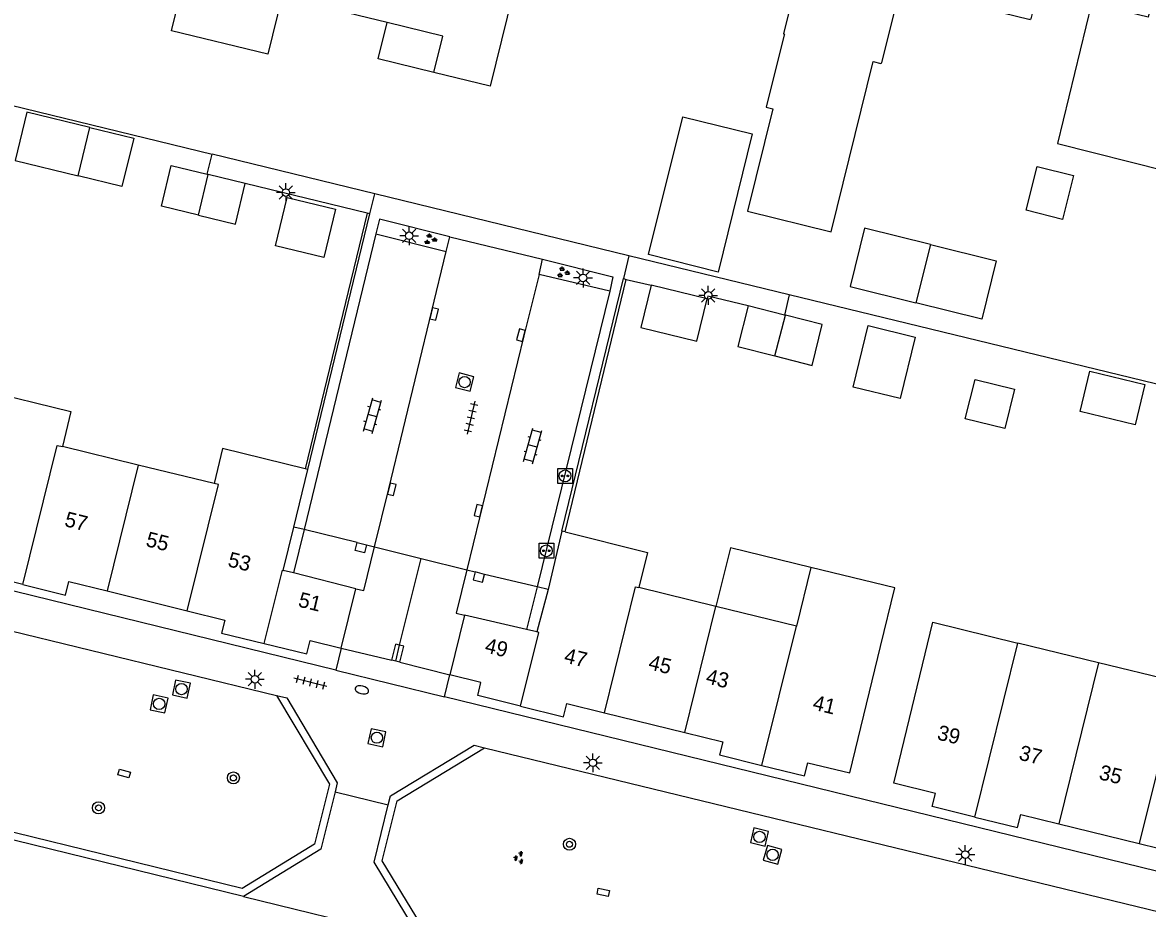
# Model space of a CAD drawing. Extents: x 125000 to 129004, y 397500 to 399008.
# Drawn here: x 126600.2 to 126674.8, y 398127.6 to 398186.4 of the extents above; entities that cross this region are included whole.
import ezdxf

# ---------------------------------------------------------------- set-up
doc = ezdxf.new("R2010")
doc.units = 0
for name, color, linetype in [('gg-afsc-erfafscheiding', 7, 'Continuous'), ('gg-afsc-hekwerk', 7, 'Continuous'), ('gg-anno-huisnummerreeks BGT', 7, 'Continuous'), ('gg-bbg-bijgebouw', 7, 'Continuous'), ('gg-bbg-gedigitaliseerde bebouwing', 7, 'Continuous'), ('gg-bbg-gedigitaliseerde bijgebouw', 7, 'Continuous'), ('gg-bbg-hoofdgebouw', 7, 'Continuous'), ('gg-bbg-luifel en loopbrug', 7, 'Continuous'), ('gg-bbg-onder overbouw', 7, 'Continuous'), ('gg-bbg-pand overbouw', 7, 'Continuous'), ('gg-bbg-pilaar onder overbouw', 7, 'Continuous'), ('gg-bbg-pilaar pand', 7, 'Continuous'), ('gg-bbg-tussenscheiding', 7, 'Continuous'), ('gg-bbg-tussenscheiding niveau 01', 7, 'Continuous'), ('gg-knt-verharding', 7, 'Continuous'), ('gg-knt-verharding onder overbouw', 7, 'Continuous'), ('gt-grn-weggrens', 7, 'Continuous'), ('gt-symb-boom', 7, 'Continuous'), ('gt-symb-brandkraan', 7, 'Continuous'), ('gt-symb-groenvak', 7, 'Continuous'), ('gt-symb-klinker verharding', 7, 'Continuous'), ('gt-symb-kolk', 7, 'Continuous'), ('gt-symb-kolk center center', 7, 'Continuous'), ('gt-symb-laadpunt elektrisch vervoer', 7, 'Continuous'), ('gt-symb-lichtmast', 7, 'Continuous'), ('gt-symb-rioolschacht', 7, 'Continuous'), ('gt-symb-tegel verharding', 7, 'Continuous')]:
    doc.layers.add(name, color=color, linetype=linetype)

# ---------------------------------------------------------------- blocks, each defined once
blk = doc.blocks.new('gt0-LMAST')
at = {"layer": 'gt-symb-lichtmast'}
for p, q in [((-0.182, 0.173), (-0.447, 0.438)), ((-0.005, 0.246), (-0.005, 0.621)), ((0.172, 0.173), (0.437, 0.438)), ((-0.255, -0.004), (-0.63, -0.004)), ((-0.182, -0.181), (-0.447, -0.446)), ((-0.005, -0.254), (-0.005, -0.629)), ((0.437, -0.446), (0.172, -0.181)), ((0.245, -0.004), (0.62, -0.004))]:
    blk.add_line(p, q, dxfattribs=at)
blk.add_circle((-0.005, -0.004), 0.25, dxfattribs=at)
blk = doc.blocks.new('gt0-GRVAK')
at = {"layer": 'gt-symb-groenvak'}
for p, q in [((-0.11, 0.189), (-0.228, 0.24)), ((-0.182, 0.153), (0.088, 0.153)), ((-0.091, 0.211), (-0.156, 0.322)), ((-0.047, 0.214), (-0.047, 0.393)), ((-0.004, 0.211), (0.061, 0.322)), ((0.015, 0.189), (0.133, 0.24)), ((0.262, -0.052), (0.197, 0.059)), ((0.305, -0.049), (0.305, 0.13)), ((0.349, -0.052), (0.414, 0.059)), ((-0.245, -0.228), (-0.363, -0.177)), ((-0.318, -0.264), (-0.047, -0.264)), ((-0.226, -0.206), (-0.291, -0.095)), ((-0.183, -0.203), (-0.183, -0.024)), ((-0.139, -0.206), (-0.074, -0.095)), ((-0.12, -0.228), (-0.002, -0.177)), ((0.243, -0.074), (0.125, -0.023)), ((0.17, -0.11), (0.441, -0.11)), ((0.368, -0.074), (0.486, -0.023))]:
    blk.add_line(p, q, dxfattribs=at)
blk = doc.blocks.new('gt0-KOLK')
at = {"layer": 'gt-symb-kolk'}
blk.add_lwpolyline([(0, 0), (0.375, 0), (0.375, 0.4), (-0.375, 0.4), (-0.375, 0), (0, 0)], dxfattribs=at)
blk = doc.blocks.new('gt0-LEV')
at = {"layer": 'gt-symb-laadpunt elektrisch vervoer'}
blk.add_lwpolyline([(-0.486, 0.501), (0.486, 0.501), (0.486, -0.499), (-0.486, -0.499)], close=True, dxfattribs=at)
for centre, radius in [((0, 0), 0.393), ((-0.186, 0), 0.0566), ((0.186, 0), 0.0566)]:
    blk.add_circle(centre, radius, dxfattribs=at)
blk = doc.blocks.new('gt0-KL1')
at = {"layer": 'gt-symb-klinker verharding'}
for p, q in [((-1.15, 0.3), (1.15, 0.3)), ((-1, -0.3), (-1, 0.3)), ((-0.5, 0.3), (-0.5, 0.45)), ((0, -0.3), (0, 0.3)), ((0.5, 0.3), (0.5, 0.45)), ((1, -0.3), (1, 0.3)), ((-1.15, -0.3), (1.15, -0.3)), ((-0.5, -0.45), (-0.5, -0.3)), ((0.5, -0.45), (0.5, -0.3))]:
    blk.add_line(p, q, dxfattribs=at)
blk = doc.blocks.new('gt0-TEG1')
at = {"layer": 'gt-symb-tegel verharding'}
for p, q in [((-1.125, 0), (1.125, 0)), ((-0.9, -0.25), (-0.9, 0.25)), ((-0.45, -0.25), (-0.45, 0.25)), ((0, -0.25), (0, 0.25)), ((0.45, -0.25), (0.45, 0.25)), ((0.9, -0.25), (0.9, 0.25))]:
    blk.add_line(p, q, dxfattribs=at)
blk = doc.blocks.new('gt0-RS')
at = {"layer": 'gt-symb-rioolschacht'}
blk.add_lwpolyline([(-0.5, -0.5), (0.5, -0.5), (0.5, 0.5), (-0.5, 0.5)], close=True, dxfattribs=at)
blk.add_circle((0, 0), 0.375, dxfattribs=at)
blk = doc.blocks.new('gt0-KOLKCC')
at = {"layer": 'gt-symb-kolk center center'}
blk.add_lwpolyline([(-0.375, 0.2), (0.375, 0.2), (0.375, -0.2), (-0.375, -0.2)], close=True, dxfattribs=at)
blk = doc.blocks.new('gt0-BR')
at = {"layer": 'gt-symb-brandkraan'}
for centre, radius, start, end in [((-0.244, 0), 0.206, 107.56694, 252.43307), ((0.599, -2.664), 3, 106.89205, 107.56694), ((0, -0.691), 0.938, 73.10799, 106.89205), ((-0.599, -2.664), 3, 72.43309, 73.10799), ((0.244, 0), 0.206, 287.56695, 72.43309), ((0.599, 2.664), 3, 252.43307, 253.10797), ((0, 0.691), 0.938, 253.10797, 286.89206), ((-0.599, 2.664), 3, 286.89206, 287.56695)]:
    blk.add_arc(centre, radius, start, end, dxfattribs=at)
blk = doc.blocks.new('gt0-BOOM')
at = {"layer": 'gt-symb-boom'}
for radius in [0.4, 0.2]:
    blk.add_circle((0, 0), radius, dxfattribs=at)

msp = doc.modelspace()

# ---------------------------------------------------------------- linework, layer by layer
at = {"layer": 'gg-afsc-erfafscheiding'}
for p, q in [((126612.44, 398176.327), (126612.768, 398177.653)), ((126623.054, 398173.738), (126614.949, 398175.717)), ((126640.226, 398169.348), (126641.881, 398168.958)), ((126651.043, 398168.332), (126650.74, 398166.986))]:
    msp.add_line(p, q, dxfattribs=at)
msp.add_lwpolyline([(126648.323, 398167.602), (126645.649, 398168.229), (126645.606, 398168.053)], dxfattribs=at)
at = {"layer": 'gg-afsc-hekwerk'}
for p, q in [((126588.032, 398183.677), (126612.768, 398177.653)), ((126623.55, 398175.027), (126612.768, 398177.653)), ((126640.415, 398170.92), (126623.55, 398175.027)), ((126623.054, 398173.738), (126618.927, 398156.788)), ((126651.043, 398168.332), (126640.415, 398170.92)), ((126636.179, 398152.601), (126640.226, 398169.348)), ((126676.075, 398162.236), (126651.043, 398168.332))]:
    msp.add_line(p, q, dxfattribs=at)
at = {"layer": 'gg-bbg-bijgebouw'}
for p, q in [((126612.509, 398176.31), (126612.44, 398176.327)), ((126614.949, 398175.717), (126612.509, 398176.31)), ((126645.606, 398168.053), (126641.881, 398168.958)), ((126650.74, 398166.986), (126648.323, 398167.602)), ((126650.79, 398166.973), (126650.74, 398166.986))]:
    msp.add_line(p, q, dxfattribs=at)
for points in [[(126643.991, 398180.132), (126648.588, 398179.003), (126646.331, 398169.819), (126641.712, 398171.01), (126643.991, 398180.132)], [(126611.852, 398173.601), (126609.396, 398174.196), (126610.053, 398176.907), (126612.44, 398176.327)], [(126611.852, 398173.601), (126614.307, 398173.005), (126614.949, 398175.717)], [(126641.881, 398168.958), (126641.204, 398166.152), (126644.925, 398165.248), (126645.606, 398168.053)], [(126648.323, 398167.602), (126647.635, 398164.898), (126650.101, 398164.269)], [(126650.101, 398164.269), (126652.566, 398163.64), (126653.235, 398166.351), (126650.79, 398166.973)]]:
    msp.add_lwpolyline(points, dxfattribs=at)
at = {"layer": 'gg-bbg-gedigitaliseerde bebouwing'}
for p, q in [((126652.473, 398150.24), (126651.526, 398146.354)), ((126655.056, 398136.613), (126657.109, 398144.993))]:
    msp.add_line(p, q, dxfattribs=at)
for points in [[(126650.71, 398185.575), (126649.525, 398180.77), (126649.962, 398180.662), (126648.286, 398173.865), (126653.82, 398172.5), (126656.607, 398183.801)], [(126657.109, 398144.993), (126658.056, 398148.879), (126652.473, 398150.24)]]:
    msp.add_lwpolyline(points, dxfattribs=at)
at = {"layer": 'gg-bbg-gedigitaliseerde bijgebouw'}
for p, q in [((126603.869, 398176.211), (126604.65, 398179.418)), ((126660.415, 398171.672), (126659.45, 398167.79))]:
    msp.add_line(p, q, dxfattribs=at)
for points in [[(126604.65, 398179.418), (126607.564, 398178.708), (126606.784, 398175.502), (126603.869, 398176.211)], [(126669.912, 398176.232), (126669.176, 398173.323), (126666.753, 398173.936), (126667.488, 398176.844), (126669.912, 398176.232)], [(126620.944, 398174.005), (126620.164, 398170.798), (126616.957, 398171.579), (126617.738, 398174.785), (126620.944, 398174.005)], [(126660.415, 398171.672), (126664.782, 398170.587), (126663.817, 398166.705), (126659.45, 398167.79)], [(126656.286, 398166.279), (126659.395, 398165.522), (126658.401, 398161.441), (126655.292, 398162.198), (126656.286, 398166.279)], [(126670.996, 398163.26), (126674.639, 398162.372), (126673.989, 398159.701), (126670.345, 398160.588), (126670.996, 398163.26)], [(126663.369, 398162.714), (126665.992, 398162.071), (126665.349, 398159.448), (126662.726, 398160.091), (126663.369, 398162.714)]]:
    msp.add_lwpolyline(points, dxfattribs=at)
at = {"layer": 'gg-bbg-hoofdgebouw'}
for p, q in [((126607.862, 398157.03), (126602.833, 398158.253)), ((126612.89, 398155.807), (126607.862, 398157.03)), ((126618.18, 398152.916), (126619.109, 398156.743)), ((126619.109, 398156.743), (126618.927, 398156.788)), ((126635.965, 398152.655), (126635.044, 398148.777)), ((126636.179, 398152.601), (126635.965, 398152.655)), ((126605.796, 398148.68), (126611.114, 398147.365)), ((126646.187, 398147.656), (126641.061, 398148.906)), ((126651.526, 398146.354), (126646.187, 398147.656)), ((126671.559, 398143.913), (126666.216, 398145.222)), ((126676.901, 398142.604), (126671.559, 398143.913)), ((126638.781, 398140.601), (126644.118, 398139.292)), ((126668.919, 398133.238), (126674.262, 398131.931))]:
    msp.add_line(p, q, dxfattribs=at)
for points in [[(126605.23, 398197.897), (126607.219, 398197.367), (126608.409, 398201.83), (126609.449, 398201.578), (126610.316, 398202.497), (126612.633, 398201.933), (126612.964, 398200.69), (126616.313, 398199.914), (126615.266, 398195.608), (126616.15, 398195.392), (126615.507, 398192.755), (126618.35, 398192.045), (126616.459, 398184.298), (126610.07, 398185.832), (126610.817, 398188.898), (126603.557, 398190.659)], [(126624.373, 398186.381), (126619.803, 398187.502), (126622.574, 398198.851), (126623.747, 398198.592), (126623.996, 398199.608), (126627.786, 398198.654), (126627.535, 398197.655), (126628.671, 398197.384)], [(126656.607, 398183.801), (126657.131, 398183.672), (126657.143, 398183.72), (126657.192, 398183.708), (126658.423, 398188.715), (126667.028, 398186.6), (126667.041, 398186.648), (126667.089, 398186.636), (126668.389, 398191.867), (126668.341, 398191.879), (126668.353, 398191.928), (126663.429, 398193.151), (126663.729, 398194.365), (126663.68, 398194.377), (126663.692, 398194.426), (126656.129, 398196.29), (126656.117, 398196.242), (126656.069, 398196.254), (126655.286, 398193.093)], [(126629.636, 398193.276), (126630.297, 398193.115), (126629.869, 398191.386), (126630.352, 398191.267), (126629.793, 398189.007), (126632.716, 398188.289), (126631.212, 398182.165), (126627.476, 398183.078)], [(126655.286, 398193.093), (126652.718, 398193.716), (126652.706, 398193.667), (126652.658, 398193.679), (126650.674, 398185.636), (126650.722, 398185.624), (126650.71, 398185.575)], [(126683.343, 398190.384), (126679.957, 398191.213), (126679.791, 398190.533), (126676.002, 398191.461), (126674.85, 398186.744), (126671.106, 398187.659), (126668.837, 398178.371), (126676.036, 398176.551), (126676.992, 398180.332), (126680.643, 398179.472)], [(126627.476, 398183.078), (126628.062, 398185.477), (126624.373, 398186.381)], [(126600.214, 398149.107), (126597.381, 398149.808), (126597.597, 398150.682), (126594.821, 398151.362), (126597.421, 398162.042), (126603.401, 398160.585), (126602.833, 398158.253)], [(126618.927, 398156.788), (126613.455, 398158.129), (126612.89, 398155.807)], [(126636.179, 398152.601), (126641.644, 398151.234), (126641.061, 398148.906)], [(126600.214, 398149.107), (126603.046, 398148.407), (126603.257, 398149.308), (126605.796, 398148.68)], [(126611.114, 398147.365), (126613.604, 398146.749), (126613.392, 398145.889), (126616.223, 398145.203)], [(126663.361, 398133.678), (126660.528, 398134.377), (126660.743, 398135.25), (126657.973, 398135.922), (126660.567, 398146.607), (126666.216, 398145.222)], [(126616.223, 398145.203), (126619.054, 398144.516), (126619.266, 398145.39), (126621.322, 398144.881)], [(126633.228, 398141.037), (126630.384, 398141.735), (126630.593, 398142.61), (126628.543, 398143.108)], [(126633.228, 398141.037), (126636.071, 398140.34), (126636.285, 398141.214), (126638.781, 398140.601)], [(126644.118, 398139.292), (126646.631, 398138.675), (126646.419, 398137.803), (126649.239, 398137.108)], [(126649.239, 398137.108), (126652.059, 398136.412), (126652.275, 398137.286), (126655.056, 398136.613)], [(126663.361, 398133.678), (126666.194, 398132.978), (126666.409, 398133.852), (126668.919, 398133.238)], [(126674.262, 398131.931), (126676.772, 398131.317), (126676.562, 398130.467), (126679.394, 398129.773)]]:
    msp.add_lwpolyline(points, dxfattribs=at)
at = {"layer": 'gg-bbg-luifel en loopbrug'}
for points in [[(126627.476, 398183.078), (126623.785, 398183.983), (126624.373, 398186.381)], [(126604.65, 398179.418), (126600.472, 398180.435), (126599.691, 398177.229), (126603.869, 398176.211)], [(126660.415, 398171.672), (126656.047, 398172.757), (126655.083, 398168.876), (126659.45, 398167.79)], [(126652.473, 398150.24), (126647.141, 398151.547), (126646.187, 398147.656)]]:
    msp.add_lwpolyline(points, dxfattribs=at)
at = {"layer": 'gg-bbg-onder overbouw'}
for p, q in [((126617.483, 398150.048), (126618.18, 398152.916)), ((126618.166, 398149.874), (126617.483, 398150.048)), ((126622.29, 398148.825), (126618.166, 398149.874)), ((126621.322, 398144.881), (126622.29, 398148.825)), ((126635.044, 398148.777), (126634.298, 398145.958)), ((126629.505, 398147.066), (126628.543, 398143.108)), ((126633.628, 398146.113), (126629.505, 398147.066)), ((126634.298, 398145.958), (126633.628, 398146.113))]:
    msp.add_line(p, q, dxfattribs=at)
at = {"layer": 'gg-bbg-pand overbouw'}
for p, q in [((126618.864, 398152.749), (126618.18, 398152.916)), ((126622.386, 398151.888), (126618.864, 398152.749)), ((126623.008, 398151.736), (126623.541, 398151.604)), ((126623.541, 398151.604), (126626.628, 398150.842)), ((126626.628, 398150.842), (126629.662, 398150.084)), ((126629.662, 398150.084), (126630.213, 398149.947)), ((126634.324, 398148.948), (126630.842, 398149.777)), ((126635.044, 398148.777), (126634.324, 398148.948)), ((126621.322, 398144.881), (126624.687, 398144.091)), ((126625.212, 398143.96), (126628.543, 398143.108))]:
    msp.add_line(p, q, dxfattribs=at)
at = {"layer": 'gg-bbg-pilaar onder overbouw'}
for p, q in [((126623.008, 398151.736), (126622.88, 398151.211)), ((126630.213, 398149.947), (126630.072, 398149.426)), ((126624.687, 398144.091), (126624.95, 398145.147)), ((126625.203, 398145.084), (126624.95, 398145.147))]:
    msp.add_line(p, q, dxfattribs=at)
for points in [[(126622.88, 398151.211), (126622.258, 398151.363), (126622.386, 398151.888)], [(126630.072, 398149.426), (126630.701, 398149.256), (126630.842, 398149.777)], [(126625.212, 398143.96), (126625.475, 398145.017), (126625.203, 398145.084)]]:
    msp.add_lwpolyline(points, dxfattribs=at)
at = {"layer": 'gg-bbg-pilaar pand'}
for p, q in [((126622.386, 398151.888), (126623.008, 398151.736)), ((126630.842, 398149.777), (126630.213, 398149.947)), ((126624.942, 398144.027), (126624.687, 398144.091)), ((126625.212, 398143.96), (126624.942, 398144.027))]:
    msp.add_line(p, q, dxfattribs=at)
at = {"layer": 'gg-bbg-tussenscheiding'}
for p, q in [((126611.852, 398173.601), (126612.509, 398176.31)), ((126650.101, 398164.269), (126650.79, 398166.973)), ((126607.862, 398157.03), (126605.796, 398148.68)), ((126644.118, 398139.292), (126646.187, 398147.656)), ((126649.239, 398137.108), (126651.526, 398146.354)), ((126663.361, 398133.678), (126666.216, 398145.222)), ((126671.559, 398143.913), (126668.919, 398133.238)), ((126676.901, 398142.604), (126674.262, 398131.931))]:
    msp.add_line(p, q, dxfattribs=at)
for points in [[(126600.214, 398149.107), (126602.496, 398158.335), (126602.833, 398158.253)], [(126611.114, 398147.365), (126613.184, 398155.735), (126612.89, 398155.807)], [(126616.223, 398145.203), (126617.425, 398150.063), (126617.483, 398150.048)], [(126638.781, 398140.601), (126640.848, 398148.958), (126641.061, 398148.906)], [(126633.228, 398141.037), (126634.436, 398145.926), (126634.298, 398145.958)]]:
    msp.add_lwpolyline(points, dxfattribs=at)
at = {"layer": 'gg-bbg-tussenscheiding niveau 01'}
for p, q in [((126625.203, 398145.084), (126626.628, 398150.842)), ((126624.942, 398144.027), (126625.203, 398145.084))]:
    msp.add_line(p, q, dxfattribs=at)
at = {"layer": 'gg-knt-verharding'}
for p, q in [((126619.109, 398156.743), (126623.233, 398173.704)), ((126623.233, 398173.704), (126623.054, 398173.738)), ((126623.626, 398172.368), (126618.864, 398152.749)), ((126623.626, 398172.368), (126628.286, 398171.198)), ((126628.286, 398171.198), (126628.527, 398172.179)), ((126634.464, 398169.673), (126634.679, 398170.68)), ((126639.135, 398168.557), (126634.464, 398169.673)), ((126635.965, 398152.655), (126640.056, 398169.397)), ((126640.056, 398169.397), (126640.226, 398169.348)), ((126639.135, 398168.557), (126634.324, 398148.948)), ((126620.969, 398143.423), (126565.056, 398157.116)), ((126567.567, 398153.779), (126617.035, 398141.755)), ((126621.322, 398144.881), (126620.969, 398143.423)), ((126628.185, 398141.655), (126628.543, 398143.108)), ((126617.035, 398141.755), (126620.539, 398135.859)), ((126684.136, 398127.951), (126628.185, 398141.655)), ((126614.761, 398128.948), (126563.773, 398141.412)), ((126625.032, 398134.764), (126630.825, 398138.278)), ((126630.825, 398138.278), (126680.19, 398126.269)), ((126614.844, 398128.413), (126581.41, 398136.586)), ((126620.929, 398135.358), (126624.451, 398134.496))]:
    msp.add_line(p, q, dxfattribs=at)
for points in [[(126628.527, 398172.179), (126623.862, 398173.339), (126623.626, 398172.368)], [(126623.541, 398151.604), (126624.49, 398155.465), (126628.286, 398171.198)], [(126634.679, 398170.68), (126639.352, 398169.52), (126639.135, 398168.557)], [(126634.464, 398169.673), (126633.44, 398165.599), (126629.662, 398150.084)], [(126617.035, 398141.755), (126617.715, 398141.59), (126621.063, 398135.955), (126620.929, 398135.358)], [(126624.451, 398134.496), (126624.587, 398135.079), (126630.137, 398138.445), (126630.825, 398138.278)], [(126620.539, 398135.859), (126619.544, 398131.872), (126614.761, 398128.948)], [(126620.929, 398135.358), (126619.98, 398131.552), (126614.844, 398128.413)], [(126626.641, 398125.535), (126623.513, 398130.69), (126624.451, 398134.496)], [(126626.961, 398125.971), (126624.048, 398130.772), (126625.032, 398134.764)]]:
    msp.add_lwpolyline(points, dxfattribs=at)
at = {"layer": 'gg-knt-verharding onder overbouw'}
for p, q in [((126618.864, 398152.749), (126618.166, 398149.874)), ((126634.324, 398148.948), (126633.628, 398146.113))]:
    msp.add_line(p, q, dxfattribs=at)
for points in [[(126622.29, 398148.825), (126622.829, 398148.709), (126623.541, 398151.604)], [(126629.662, 398150.084), (126628.954, 398147.206), (126629.505, 398147.066)]]:
    msp.add_lwpolyline(points, dxfattribs=at)
at = {"layer": 'gt-grn-weggrens'}
for p, q in [((126623.233, 398173.704), (126623.55, 398175.027)), ((126628.527, 398172.179), (126634.679, 398170.68)), ((126640.415, 398170.92), (126640.056, 398169.397)), ((126620.969, 398143.423), (126628.185, 398141.655)), ((126614.844, 398128.413), (126626.641, 398125.535))]:
    msp.add_line(p, q, dxfattribs=at)

# ---------------------------------------------------------------- block references
at = {"layer": 'gt-symb-boom'}
for p in [(126614.175, 398136.278), (126605.229, 398134.291), (126636.467, 398131.876)]:
    msp.add_blockref('gt0-BOOM', p, dxfattribs=at)
at = {"layer": 'gt-symb-brandkraan', "rotation": 165.2826888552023}
msp.add_blockref('gt0-BR', (126622.696, 398142.121), dxfattribs=at)
at = {"layer": 'gt-symb-groenvak'}
for p in [(126627.223, 398172.008), (126636.037, 398169.815)]:
    msp.add_blockref('gt0-GRVAK', p, dxfattribs=at)
at = {"layer": 'gt-symb-groenvak', "rotation": 75.7552575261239}
msp.add_blockref('gt0-GRVAK', (126633.14, 398130.948), dxfattribs=at)
at = {"layer": 'gt-symb-klinker verharding'}
for p, rotation in [((126623.394, 398160.308), 74.39306952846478), ((126634.027, 398158.301), 74.39306952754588)]:
    msp.add_blockref('gt0-KL1', p, dxfattribs=dict(at, rotation=rotation))
at = {"layer": 'gt-symb-kolk'}
for p, rotation in [((126627.299, 398167.1), -103.59156043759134), ((126633.44, 398165.599), 75.88039706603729), ((126624.49, 398155.465), -103.82779503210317), ((126630.614, 398153.956), 76.35276166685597)]:
    msp.add_blockref('gt0-KOLK', p, dxfattribs=dict(at, rotation=rotation))
at = {"layer": 'gt-symb-kolk center center'}
for p, rotation in [((126606.929, 398136.572), 165.04643524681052), ((126638.707, 398128.692), -11.882758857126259)]:
    msp.add_blockref('gt0-KOLKCC', p, dxfattribs=dict(at, rotation=rotation))
at = {"layer": 'gt-symb-laadpunt elektrisch vervoer'}
for p in [(126636.175, 398156.313), (126634.938, 398151.344)]:
    msp.add_blockref('gt0-LEV', p, dxfattribs=at)
at = {"layer": 'gt-symb-lichtmast'}
for p in [(126617.658, 398175.112), (126625.841, 398172.253), (126637.373, 398169.447), (126645.676, 398168.292), (126615.607, 398142.827), (126638.025, 398137.281), (126662.728, 398131.192)]:
    msp.add_blockref('gt0-LMAST', p, dxfattribs=at)
at = {"layer": 'gt-symb-rioolschacht'}
for p, rotation in [((126629.512, 398162.534), 75.64421500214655), ((126610.731, 398142.168), -11.882758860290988), ((126609.25, 398141.189), 78.22937399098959), ((126623.699, 398138.947), 167.2972680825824), ((126649.074, 398132.361), -103.29958432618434), ((126649.941, 398131.175), -105.84308211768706)]:
    msp.add_blockref('gt0-RS', p, dxfattribs=dict(at, rotation=rotation))
at = {"layer": 'gt-symb-tegel verharding'}
for p, rotation in [((126629.932, 398160.184), -103.24380202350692), ((126619.282, 398142.609), 165.75525752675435)]:
    msp.add_blockref('gt0-TEG1', p, dxfattribs=dict(at, rotation=rotation))

# ---------------------------------------------------------------- texts
at = {"layer": 'gg-anno-huisnummerreeks BGT'}
for s, rotation, p in [('57', 346.1, (126602.915, 398152.995)), ('55', 346.1, (126608.31, 398151.665)), ('53', 346.1, (126613.746, 398150.324)), ('51', 346.1, (126618.417, 398147.657)), ('49', 346.3, (126630.791, 398144.618)), ('47', 346.2, (126636.052, 398143.948)), ('45', 346.2, (126641.647, 398143.501)), ('43', 346.2, (126645.454, 398142.567)), ('41', 346.4, (126652.543, 398140.826)), ('39', 346.4, (126660.798, 398138.838)), ('37', 346.3, (126666.221, 398137.5)), ('35', 346.2, (126671.534, 398136.201))]:
    msp.add_text(s, height=1, rotation=rotation, dxfattribs=at).set_placement(p)

doc.saveas('drawing.dxf')
